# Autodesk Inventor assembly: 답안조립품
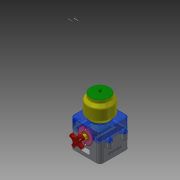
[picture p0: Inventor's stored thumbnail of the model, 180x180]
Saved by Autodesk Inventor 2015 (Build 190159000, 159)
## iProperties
Created: 2022-03
Part Number: 답안조립품
Document SubType Name: Assembly
Designer: pc-04
Author: pc-04
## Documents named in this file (11)
- C:\Users\pc-04\Desktop\720306V1026\답안조립품.iam
- C:\Users\pc-04\Desktop\720306V1026\본체.ipt
- C:\Users\pc-04\Desktop\720306V1026\베어링 부시.ipt
- C:\Users\pc-04\Desktop\720306V1026\본체커버.ipt
- C:\Users\pc-04\Desktop\720306V1026\볼트 M3x12.ipt
- C:\Users\pc-04\Desktop\720306V1026\볼트 M4x12.ipt
- C:\Users\pc-04\Desktop\720306V1026\앞커버.ipt
- C:\Users\pc-04\Desktop\720306V1026\용기.ipt
- C:\Users\pc-04\Desktop\720306V1026\용기캡.ipt
- C:\Users\pc-04\Desktop\720306V1026\핸들.ipt
- C:\Users\pc-04\Desktop\720306V1026\핸들축.ipt
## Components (2 placed, 2 different names)
1. 핸들:1
2. 핸들축:1
